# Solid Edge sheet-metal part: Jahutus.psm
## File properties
Author: Indrek
Template: Normal.psm
Last saved by: Indrek
Revision: 1
Application: Solid Edge
Accuracy: 0,990
Material Thickness: 1,00 mm
Bend Radius: 1,00 mm
Relief Width: 1,00 mm
Relief Length: 0,00 mm
Neutral Factor: 0,330
Minimum Arc Length: 0,10 mm
Deviational Tolerance: 0,10 mm
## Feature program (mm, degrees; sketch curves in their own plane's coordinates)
base tab "unnamed BaseTab 1"
louver "Louver_4"  LouverHeight = 27.5687 mm
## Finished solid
Body 1: solid body, 14 faces, 34 edges, 22 vertices.
  Faces by surface: plane 8, sphere 4, cylinder 2
  Edges by curve: line 20, circle 14
Bounding box of the edges (mm; curved faces can reach further): 28.569 x 100.000 x 100.000, from (0, -61.9765, 57) to (28.5687, 38.0235, 157).
Cylindrical faces by radius (mm): R34.0106 x1, R35.0106 x1
Spherical faces by radius (mm): R34.0106 x2, R35.0106 x2
Planar faces by outward normal: +x 1, +y 1, +z 2, -x 1, -y 1, -z 2
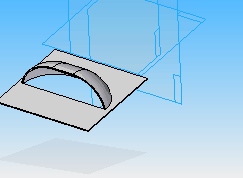
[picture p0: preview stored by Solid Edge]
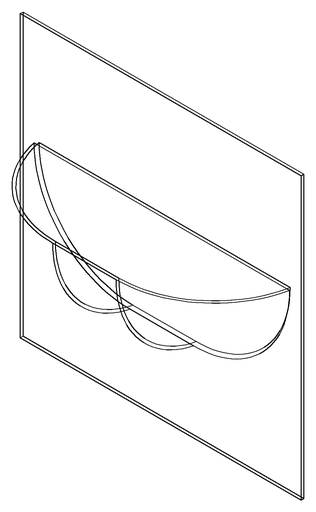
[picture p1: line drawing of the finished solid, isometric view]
